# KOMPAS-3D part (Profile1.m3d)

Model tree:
1. Plane XY
2. Plane ZX
3. Plane ZY
4. X Axis
5. Y Axis
6. Z Axis
7. Origin
8. Sketch:1
9. Extrude:1
     Wall Thickness 1 = 1; Wall Thickness 2 = 1; Distance 1 = 6800; Distance 2 = 10
10. Three Point Plane:1
11. Sketch:2
12. Extrude:2
     Wall Thickness 1 = 1; Wall Thickness 2 = 1; Distance 1 = 190; Distance 2 = 10
13. Three Point Plane:2
14. Sketch:3
15. Extrude:3
     Wall Thickness 1 = 1; Wall Thickness 2 = 1; Distance 1 = 190; Distance 2 = 10

Referenced files in D:\Documents and Settings\kashirsky\Рабочий стол\Seminar\: Cottage_balcony.a3d
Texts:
  Steel DIN 17102
  Three Point Plane
  Plane at Angle
  Line and Point Plane
  Axis through Two Vertices
  Axis of Feature
  Axis of Conical Surface
  Axis through Edge
  Trim by Surface
  Trim by Sketch
  Feature with No History
  Intersection Axis of Two Planes
  Two Line Plane
  Line and Face Plane
  Bend by line
  Hole in sheet body
  Cut in sheet body
  Point in CM
  Linear Dimension from Line to Point
  Surface Finish Symbol
  Geometric Tolerance Symbol
  Leader #1
  Leader #2
  Leader #3
  Shape Deviations and Datum
  Node point number
  Mark of coordination axis
  Node point designation
  Mark/Reference designation with leader
  Mark/reference designation on line
  Mark/Reference designation without leader
  CONTINUOUS_RGB_255_0_0_THICK_0.18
